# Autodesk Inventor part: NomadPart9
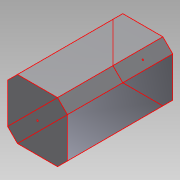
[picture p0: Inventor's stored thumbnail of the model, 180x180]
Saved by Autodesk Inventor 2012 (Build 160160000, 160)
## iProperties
Created: 2012-10
Part Number: NomadPart9
Material: Default
Document SubType Name: Modeling
Designer: TechShop Member
Density: 1 g/cm^3
Author: TechShop Member
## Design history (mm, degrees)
sketch "MainBody"
  geometry: L1 (-13.7, -9.923)-(-51.482, 27.859); L2 (-13.7, -9.923)-(39.731, -9.923); L3 (-51.482, 27.859)-(-51.482, 181.348); L4 (-51.482, 181.348)-(-13.7, 219.13); L5 (-13.7, 219.13)-(139.789, 219.13); L6 (139.789, 219.13)-(177.571, 181.348); L7 (177.571, 181.348)-(177.571, 27.859); L8 (177.571, 27.859)-(139.789, -9.923); L9 (139.789, -9.923)-(-13.7, -9.923); 1 further point
  constraints: 18 end point, 5 perpendicular, 1 equal length, 1 horizontal, 1 vertical
  dimensions: "d0" = 53.43144 distance of L1.start L1.end; "d1" = 135 deg angle of L2 L1; "d2" = 153.48966 distance of L1.end L3.end; "d3" = 53.43144 distance of L3.end L4.end; "d4" = 153.48966 distance of L4.end L5.end; "d5" = 53.43144 distance of L5.end L6.end; "d6" = 153.48966 distance of L6.end L7.end; "d7" = 53.43144 distance of L7.end L8.end; "d8" = 135 deg angle of L7 L8 (derived)
extrude "Extrusion1" new body sketch "MainBody" distance "d9" = 403.225; taper "d10" = 0 deg
sketch "Sketch2"
  geometry: 2 further points
hole "Hole1" sketch "Sketch2" at (63.044, 104.603) diameter "d11" = 5.207; stored, may be unused: countersink angle "d15" = 82 deg, drill point angle "d17" = 118 deg; dims "d12" = 19.05, "d13" = 9.525, "d14" = 6.35, "d16" = 25.4
body "Solid1"
